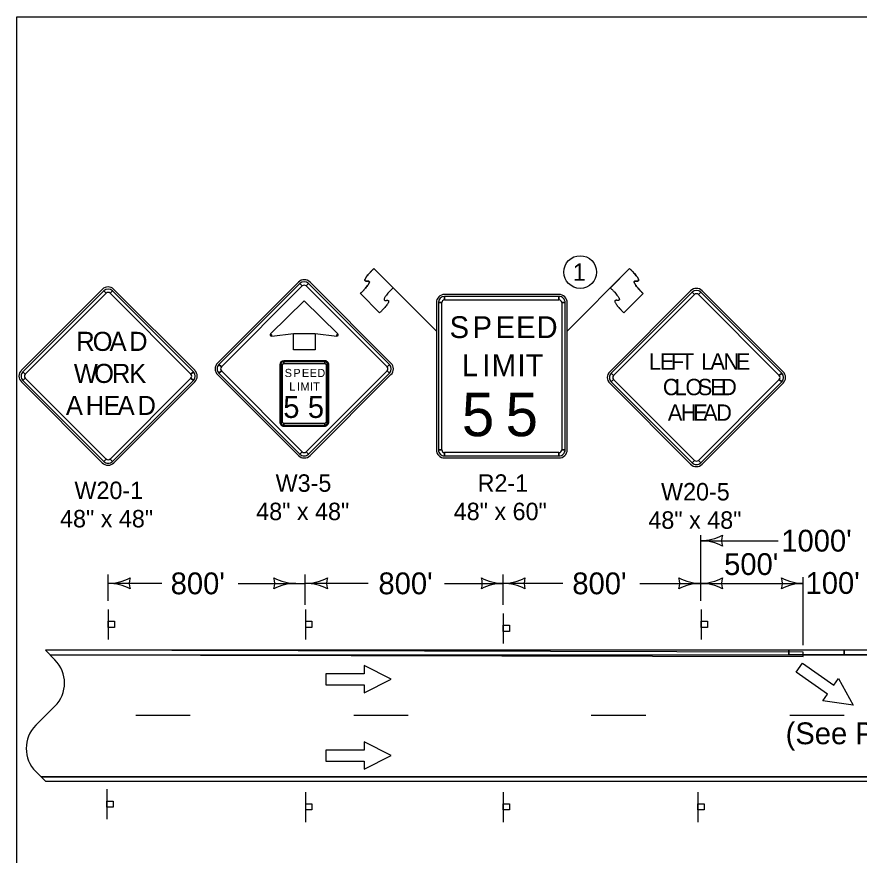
# Model space of a CAD drawing. Extents: x 10133 to 2270741, y 5363 to 1733450.
# Drawn here: x 24533 to 25305, y 9175 to 9944 of the extents above; entities that cross this region are included whole.
import ezdxf

# ---------------------------------------------------------------- set-up
doc = ezdxf.new("R2010")
doc.units = 0
for name, color, linetype in [('dsnNonPlotable', 7, 'Continuous'), ('dsnShtPlotShapeBatchPrint', 7, 'Continuous'), ('dsnStdBorder', 7, 'Continuous'), ('Level 12', 7, 'Continuous'), ('Level 2', 7, 'Continuous'), ('SheetBorder', 7, 'Continuous'), ('SheetText', 7, 'Continuous')]:
    doc.layers.add(name, color=color, linetype=linetype)

msp = doc.modelspace()

# ---------------------------------------------------------------- linework, layer by layer
at = {"layer": 'dsnNonPlotable'}
for p, q in [((24567.46, 9354.26), (24558.68, 9363.04)), ((24562.66, 9359.06), (25758.9, 9359.06)), ((25247.47, 9342.98), (25253.2, 9351.18)), ((25253.2, 9351.18), (25281.87, 9331.11)), ((25276.13, 9322.91), (25247.47, 9342.98)), ((25281.87, 9331.11), (25286.17, 9337.25)), ((25286.17, 9337.25), (25299.48, 9312.67)), ((25271.83, 9316.77), (25276.13, 9322.91)), ((24549.89, 9294.27), (24567.46, 9311.84)), ((25299.48, 9312.67), (25271.83, 9316.77)), ((24558.68, 9243.06), (24549.89, 9251.85)), ((24554.7, 9247.04), (26172.85, 9247.04))]:
    msp.add_line(p, q, dxfattribs=at)
for points in [[(24641.51, 9303.46), (24691.5, 9303.46)], [(24841.48, 9303.46), (24891.47, 9303.46)], [(25059.45, 9303.46), (25109.44, 9303.46)], [(25241.41, 9303.46), (25291.41, 9303.46)]]:
    msp.add_lwpolyline(points, dxfattribs=at)
for centre, start, end in [((24546.25, 9333.05), 315, 45), ((24571.1, 9273.06), 135, 225)]:
    msp.add_arc(centre, 30, start, end, dxfattribs=at)
at = {"layer": 'dsnShtPlotShapeBatchPrint'}
msp.add_circle((25049.25, 9709.97), 15, dxfattribs=at)
at = {"layer": 'dsnStdBorder'}
for p, q in [((24917.3, 9655.88), (24859.98, 9713.2)), ((24859.98, 9713.2), (24877.67, 9695.51)), ((25037.3, 9655.88), (25094.62, 9713.2)), ((25094.62, 9713.2), (25076.94, 9695.51)), ((24790.82, 9700.73), (24716.58, 9626.48)), ((24792.15, 9699.4), (24794.36, 9697.19)), ((24797.9, 9697.19), (24800.1, 9699.4)), ((24875.68, 9626.48), (24801.43, 9700.73)), ((24610.92, 9694.07), (24536.67, 9619.83)), ((24612.24, 9692.75), (24614.45, 9690.54)), ((24617.99, 9690.54), (24620.2, 9692.75)), ((24695.77, 9619.83), (24621.52, 9694.07)), ((24847.61, 9690.21), (24865.28, 9672.53)), ((24865.28, 9672.53), (24847.61, 9690.21)), ((25029.8, 9689.43), (24924.8, 9689.43)), ((25150.55, 9692.82), (25076.3, 9618.57)), ((25107, 9690.21), (25089.32, 9672.53)), ((25089.32, 9672.53), (25107, 9690.21)), ((25151.87, 9691.49), (25154.08, 9689.28)), ((25157.62, 9689.28), (25159.83, 9691.49)), ((25235.4, 9618.57), (25161.15, 9692.82)), ((24917.3, 9681.93), (24917.3, 9546.93)), ((24919.18, 9681.93), (24922.3, 9681.93)), ((24924.8, 9684.43), (24924.8, 9687.56)), ((25029.8, 9687.56), (25029.8, 9684.43)), ((25032.3, 9681.93), (25035.43, 9681.93)), ((25037.3, 9546.93), (25037.3, 9681.93)), ((24766.13, 9652.43), (24765.24, 9653.31)), ((24766.28, 9651.19), (24766.13, 9652.43)), ((24826.13, 9652.43), (24825.97, 9651.19)), ((24827.01, 9653.31), (24826.13, 9652.43)), ((24814.88, 9628.68), (24777.38, 9628.68)), ((24777.38, 9626.18), (24777.38, 9627.74)), ((24814.88, 9627.74), (24814.88, 9626.18)), ((24720.11, 9622.94), (24717.9, 9625.15)), ((24717.9, 9617.2), (24720.11, 9619.41)), ((24773.63, 9624.93), (24773.63, 9572.43)), ((24774.56, 9624.93), (24776.13, 9624.93)), ((24816.13, 9624.93), (24817.69, 9624.93)), ((24818.63, 9572.43), (24818.63, 9624.93)), ((24874.35, 9625.15), (24872.14, 9622.94)), ((24872.14, 9619.41), (24874.35, 9617.2)), ((24540.21, 9616.29), (24538, 9618.5)), ((24538, 9610.55), (24540.21, 9612.76)), ((24694.44, 9618.5), (24692.24, 9616.29)), ((24692.24, 9612.76), (24694.44, 9610.55)), ((24716.58, 9615.87), (24790.82, 9541.63)), ((24801.43, 9541.63), (24875.68, 9615.87)), ((25079.83, 9615.04), (25077.63, 9617.25)), ((25077.63, 9609.29), (25079.83, 9611.5)), ((25234.07, 9617.25), (25231.86, 9615.04)), ((25231.86, 9611.5), (25234.07, 9609.29)), ((24536.67, 9609.22), (24610.92, 9534.97)), ((24621.52, 9534.97), (24695.77, 9609.22)), ((25076.3, 9607.97), (25150.55, 9533.72)), ((25161.15, 9533.72), (25235.4, 9607.97)), ((24776.13, 9572.43), (24774.56, 9572.43)), ((24817.69, 9572.43), (24816.13, 9572.43)), ((24777.38, 9569.61), (24777.38, 9571.18)), ((24777.38, 9568.68), (24814.88, 9568.68)), ((24814.88, 9571.18), (24814.88, 9569.61)), ((24794.36, 9545.16), (24792.15, 9542.95)), ((24800.1, 9542.95), (24797.9, 9545.16)), ((24922.3, 9546.93), (24919.18, 9546.93)), ((24924.8, 9541.31), (24924.8, 9544.43)), ((25029.8, 9544.43), (25029.8, 9541.31)), ((25035.43, 9546.93), (25032.3, 9546.93)), ((24614.45, 9538.51), (24612.24, 9536.3)), ((24620.2, 9536.3), (24617.99, 9538.51)), ((24924.8, 9539.43), (25029.8, 9539.43)), ((25154.08, 9537.26), (25151.87, 9535.05)), ((25159.83, 9535.05), (25157.62, 9537.26)), ((24616.22, 9400.56), (24616.22, 9373.06)), ((24797.42, 9400.56), (24797.42, 9373.06)), ((24978.61, 9396.83), (24978.61, 9369.33)), ((25160.24, 9400.56), (25160.24, 9373.06)), ((24615.02, 9235.59), (24615.02, 9208.09)), ((24797.42, 9233.06), (24797.42, 9205.56)), ((24978.59, 9233.06), (24978.59, 9205.56)), ((25157.14, 9233.06), (25157.14, 9205.56))]:
    msp.add_line(p, q, dxfattribs=at)
for points in [[(24792.15, 9699.4), (24717.9, 9625.15), (24720.11, 9622.94), (24794.36, 9697.19), (24792.15, 9699.4)], [(24874.35, 9625.15), (24800.1, 9699.4), (24797.9, 9697.19), (24872.14, 9622.94), (24874.35, 9625.15)], [(24612.24, 9692.75), (24538, 9618.5), (24540.21, 9616.29), (24614.45, 9690.54), (24612.24, 9692.75)], [(24694.44, 9618.5), (24620.2, 9692.75), (24617.99, 9690.54), (24692.24, 9616.29), (24694.44, 9618.5)], [(25151.87, 9691.49), (25077.63, 9617.25), (25079.83, 9615.04), (25154.08, 9689.28), (25151.87, 9691.49)], [(25234.07, 9617.25), (25159.83, 9691.49), (25157.62, 9689.28), (25231.86, 9615.04), (25234.07, 9617.25)], [(24796.13, 9683.68), (24765.24, 9653.31), (24766.13, 9652.43), (24766.28, 9651.19), (24786.13, 9653.68), (24806.13, 9653.68), (24825.97, 9651.19), (24826.13, 9652.43), (24827.01, 9653.31), (24796.13, 9683.68)], [(24919.18, 9681.93), (24919.18, 9546.93), (24922.3, 9546.93), (24922.3, 9681.93), (24919.18, 9681.93)], [(25029.8, 9687.56), (24924.8, 9687.56), (24924.8, 9684.43), (25029.8, 9684.43), (25029.8, 9687.56)], [(25035.43, 9546.93), (25035.43, 9681.93), (25032.3, 9681.93), (25032.3, 9546.93), (25035.43, 9546.93)], [(24806.13, 9638.68), (24786.13, 9638.68), (24786.13, 9653.68), (24806.13, 9653.68), (24806.13, 9638.68)], [(24814.88, 9627.74), (24777.38, 9627.74), (24777.38, 9626.18), (24814.88, 9626.18), (24814.88, 9627.74)], [(24717.9, 9617.2), (24792.15, 9542.95), (24794.36, 9545.16), (24720.11, 9619.41), (24717.9, 9617.2)], [(24774.56, 9624.93), (24774.56, 9572.43), (24776.13, 9572.43), (24776.13, 9624.93), (24774.56, 9624.93)], [(24800.1, 9542.95), (24874.35, 9617.2), (24872.14, 9619.41), (24797.9, 9545.16), (24800.1, 9542.95)], [(24817.69, 9572.43), (24817.69, 9624.93), (24816.13, 9624.93), (24816.13, 9572.43), (24817.69, 9572.43)], [(24538, 9610.55), (24612.24, 9536.3), (24614.45, 9538.51), (24540.21, 9612.76), (24538, 9610.55)], [(24620.2, 9536.3), (24694.44, 9610.55), (24692.24, 9612.76), (24617.99, 9538.51), (24620.2, 9536.3)], [(25077.63, 9609.29), (25151.87, 9535.05), (25154.08, 9537.26), (25079.83, 9611.5), (25077.63, 9609.29)], [(25159.83, 9535.05), (25234.07, 9609.29), (25231.86, 9611.5), (25157.62, 9537.26), (25159.83, 9535.05)], [(24777.38, 9569.61), (24814.88, 9569.61), (24814.88, 9571.18), (24777.38, 9571.18), (24777.38, 9569.61)], [(24924.8, 9541.31), (25029.8, 9541.31), (25029.8, 9544.43), (24924.8, 9544.43), (24924.8, 9541.31)], [(24616.32, 9384.11), (24616.32, 9389.74), (24621.94, 9389.74), (24621.94, 9384.11)], [(24797.51, 9384.11), (24797.51, 9389.74), (24803.14, 9389.74), (24803.14, 9384.11)], [(25160.33, 9384.11), (25160.33, 9389.74), (25165.96, 9389.74), (25165.96, 9384.11)], [(24978.71, 9380.38), (24978.71, 9386), (24984.33, 9386), (24984.33, 9380.38)], [(24615.11, 9219.14), (24615.11, 9224.77), (24620.74, 9224.77), (24620.74, 9219.14)], [(24797.51, 9216.61), (24797.51, 9222.24), (24803.14, 9222.24), (24803.14, 9216.61)], [(24978.69, 9216.61), (24978.69, 9222.24), (24984.31, 9222.24), (24984.31, 9216.61)], [(25157.23, 9216.61), (25157.23, 9222.24), (25162.86, 9222.24), (25162.86, 9216.61)]]:
    msp.add_lwpolyline(points, close=True, dxfattribs=at)
for centre, radius, start, end in [((24616.22, 9688.77), 7.5, 44.99999, 134.99974), ((24796.13, 9695.42), 7.5, 44.99999, 134.99974), ((24796.13, 9695.42), 5.62, 44.99999, 134.99974), ((24796.13, 9695.42), 2.5, 44.99999, 134.99974), ((24616.22, 9688.77), 5.62, 44.99999, 134.99974), ((24616.22, 9688.77), 2.5, 44.99999, 134.99974), ((24924.8, 9681.93), 7.5, 90.00021, 179.99985), ((25029.8, 9681.93), 7.5, 0, 90.00021), ((25155.85, 9687.52), 7.5, 44.99999, 134.99974), ((25155.85, 9687.52), 5.62, 44.99999, 134.99974), ((25155.85, 9687.52), 2.5, 44.99999, 134.99974), ((24924.8, 9681.93), 5.62, 90.00021, 179.99985), ((24924.8, 9681.93), 2.5, 90.00021, 179.99985), ((25029.8, 9681.93), 5.62, 0, 90.00021), ((25029.8, 9681.93), 2.5, 0, 90.00021), ((24766.13, 9652.43), 1.25, 134.99974, 277.15286), ((24826.13, 9652.43), 1.25, 262.84725, 44.9998), ((24777.38, 9624.93), 3.75, 90.00021, 179.99985), ((24777.38, 9624.93), 2.81, 90.00021, 179.99985), ((24814.88, 9624.93), 3.75, 0, 90.00021), ((24814.88, 9624.93), 2.81, 0, 90.00021), ((24541.98, 9614.52), 7.5, 134.99974, 224.99995), ((24690.47, 9614.52), 7.5, 315.00016, 44.9998), ((24721.88, 9621.18), 7.5, 134.99974, 224.99995), ((24721.88, 9621.18), 5.62, 134.99974, 224.99995), ((24721.88, 9621.18), 2.5, 134.99974, 224.99995), ((24777.38, 9624.93), 1.25, 90.00021, 179.99985), ((24814.88, 9624.93), 1.25, 0, 90.00021), ((24870.37, 9621.18), 2.5, 315.00016, 44.9998), ((24870.37, 9621.18), 5.62, 315.00016, 44.9998), ((24870.37, 9621.18), 7.5, 315.00016, 44.9998), ((24541.98, 9614.52), 5.62, 134.99974, 224.99995), ((24541.98, 9614.52), 2.5, 134.99974, 224.99995), ((24690.47, 9614.52), 2.5, 315.00016, 44.9998), ((24690.47, 9614.52), 5.62, 315.00016, 44.9998), ((25081.6, 9613.27), 7.5, 134.99974, 224.99995), ((25081.6, 9613.27), 5.62, 134.99974, 224.99995), ((25081.6, 9613.27), 2.5, 134.99974, 224.99995), ((25230.09, 9613.27), 2.5, 315.00016, 44.9998), ((25230.09, 9613.27), 5.62, 315.00016, 44.9998), ((25230.09, 9613.27), 7.5, 315.00016, 44.9998), ((24777.38, 9572.43), 3.75, 179.99985, 270.00006), ((24777.38, 9572.43), 2.81, 179.99985, 270.00006), ((24777.38, 9572.43), 1.25, 179.99985, 270.00006), ((24814.88, 9572.43), 3.75, 270.00006, 0.00027), ((24814.88, 9572.43), 2.81, 270.00006, 0.00027), ((24814.88, 9572.43), 1.25, 270.00006, 0.00027), ((24796.13, 9546.93), 7.5, 224.99995, 315.00016), ((24796.13, 9546.93), 5.62, 224.99995, 315.00016), ((24796.13, 9546.93), 2.5, 224.99995, 315.00016), ((24924.8, 9546.93), 7.5, 179.99985, 270.00006), ((24924.8, 9546.93), 5.62, 179.99985, 270.00006), ((24924.8, 9546.93), 2.5, 179.99985, 270.00006), ((25029.8, 9546.93), 7.5, 270.00006, 0.00027), ((25029.8, 9546.93), 5.62, 270.00006, 0.00027), ((25029.8, 9546.93), 2.5, 270.00006, 0.00027), ((24616.22, 9540.28), 7.5, 224.99995, 315.00016), ((24616.22, 9540.28), 5.62, 224.99995, 315.00016), ((24616.22, 9540.28), 2.5, 224.99995, 315.00016), ((25155.85, 9539.02), 5.62, 224.99995, 315.00016), ((25155.85, 9539.02), 2.5, 224.99995, 315.00016), ((25155.85, 9539.02), 7.5, 224.99995, 315.00016)]:
    msp.add_arc(centre, radius, start, end, dxfattribs=at)
for points in [[(24859.98, 9713.2), (24847.61, 9700.81), (24859.98, 9702.58), (24847.61, 9690.21)], [(24847.61, 9690.21), (24859.98, 9702.58), (24847.61, 9700.81), (24859.98, 9713.2)], [(25094.62, 9713.2), (25107, 9700.81), (25094.62, 9702.58), (25107, 9690.21)], [(25107, 9690.21), (25094.62, 9702.58), (25107, 9700.81), (25094.62, 9713.2)], [(24877.67, 9695.51), (24865.29, 9683.13), (24877.66, 9684.9), (24865.28, 9672.53)], [(24877.67, 9695.51), (24865.29, 9683.13), (24877.66, 9684.9), (24865.28, 9672.53)], [(25076.94, 9695.51), (25089.32, 9683.13), (25076.95, 9684.9), (25089.32, 9672.53)], [(25076.94, 9695.51), (25089.32, 9683.13), (25076.95, 9684.9), (25089.32, 9672.53)]]:
    msp.add_open_spline(points, degree=2, dxfattribs=at)
at = {"layer": 'Level 12'}
for p, q in [((25159.79, 9408.56), (25159.79, 9468.6)), ((25159.59, 9463.6), (25230.82, 9463.6)), ((24616.22, 9408.56), (24616.22, 9432.57)), ((24797.03, 9404.83), (24797.03, 9432.57)), ((24978.61, 9404.83), (24978.61, 9432.57)), ((25253.89, 9367.79), (25253.89, 9430.03)), ((24665.58, 9424.45), (24619.02, 9424.45)), ((24735.61, 9424.45), (24797.03, 9424.45)), ((24854.89, 9424.45), (24797.03, 9424.45)), ((24924.91, 9424.45), (24978.61, 9424.45)), ((25033.2, 9424.45), (24978.61, 9424.45)), ((25103.97, 9424.45), (25159.59, 9424.45)), ((25160.39, 9424.45), (25228.11, 9424.45)), ((25228.11, 9424.45), (25253.89, 9424.45))]:
    msp.add_line(p, q, dxfattribs=at)
for centre, radius, start, end in [((25159.79, 9506.1), 42.5, 270, 298.07249), ((25195.42, 9463.6), 16.42, 162.26665, 197.73335), ((25159.79, 9421.1), 42.5, 61.92751, 90), ((24616.33, 9466.95), 42.5, 270, 298.07249), ((24651.97, 9424.45), 16.42, 162.26665, 197.73335), ((24752.68, 9424.45), 16.42, 342.26665, 17.73335), ((24788.32, 9466.95), 42.5, 241.92751, 270), ((24797.42, 9466.95), 42.5, 270, 298.07249), ((24833.05, 9424.45), 16.42, 162.26665, 197.73335), ((24942.96, 9424.45), 16.42, 342.26665, 17.73335), ((24978.59, 9466.95), 42.5, 241.92751, 270), ((24978.59, 9466.95), 42.5, 270, 298.07249), ((25014.23, 9424.45), 16.42, 162.26665, 197.73335), ((25124.15, 9424.45), 16.42, 342.26665, 17.73335), ((25159.79, 9466.95), 42.5, 241.92751, 270), ((25159.79, 9466.95), 42.5, 270, 298.07249), ((25195.42, 9424.45), 16.42, 162.26665, 197.73335), ((25218.25, 9424.45), 16.42, 342.26665, 17.73335), ((25253.89, 9466.95), 42.5, 241.92751, 270), ((24616.33, 9381.95), 42.5, 61.92751, 90), ((24788.32, 9381.95), 42.5, 90, 118.07249), ((24797.42, 9381.95), 42.5, 61.92751, 90), ((24978.59, 9381.95), 42.5, 90, 118.07249), ((24978.59, 9381.95), 42.5, 61.92751, 90), ((25159.79, 9381.95), 42.5, 90, 118.07249), ((25159.79, 9381.95), 42.5, 61.92751, 90), ((25253.89, 9381.95), 42.5, 90, 118.07249)]:
    msp.add_arc(centre, radius, start, end, dxfattribs=at)
at = {"layer": 'Level 2'}
for p, q in [((25240.68, 9363.06), (24558.68, 9363.06)), ((24558.68, 9363.06), (24567.46, 9354.26)), ((25253.89, 9361.36), (24558.68, 9363.06)), ((24562.67, 9359.06), (25253.89, 9357.36)), ((25240.68, 9359.06), (25240.68, 9363.06)), ((25291.5, 9363.06), (25240.68, 9363.06)), ((25240.68, 9363.06), (25240.68, 9359.06)), ((25240.68, 9359.06), (25291.5, 9359.06)), ((25253.89, 9357.36), (25253.89, 9361.36)), ((25483.46, 9363.06), (25291.5, 9363.06)), ((25291.5, 9363.06), (25291.5, 9359.06)), ((25291.5, 9359.06), (25291.5, 9363.06)), ((25291.5, 9359.06), (25483.46, 9359.06)), ((24567.46, 9311.84), (24549.89, 9294.27)), ((24549.89, 9251.85), (24554.68, 9247.06)), ((25938.21, 9247.06), (24554.68, 9247.06)), ((24554.68, 9247.06), (24558.68, 9243.06)), ((24554.68, 9247.06), (25389.45, 9247.06)), ((24558.68, 9243.06), (25964.98, 9243.06)), ((24558.68, 9243.06), (25936.49, 9243.06))]:
    msp.add_line(p, q, dxfattribs=at)
for points in [[(24558.68, 9363.06), (24562.66, 9359.07), (24562.67, 9359.06)], [(25389.45, 9359.06), (25291.5, 9359.06), (25240.68, 9359.06)], [(24554.68, 9247.06), (24554.68, 9247.06)], [(24554.68, 9247.06), (24554.68, 9247.06)]]:
    msp.add_lwpolyline(points, dxfattribs=at)
for centre, start, end in [((24546.25, 9333.05), 315, 45), ((24571.1, 9273.06), 135, 225)]:
    msp.add_arc(centre, 30, start, end, dxfattribs=at)
at = {"layer": 'SheetBorder'}
msp.add_lwpolyline([(24532.52, 9944.02), (27667.53, 9944.02), (27667.53, 7924.02), (24532.52, 7924.02)], close=True, dxfattribs=at)
at = {"layer": 'SheetText'}
for points in [[(24815.99, 9341.51), (24815.99, 9331.51), (24850.99, 9331.51), (24850.99, 9324.01), (24875.99, 9336.51), (24850.99, 9349.01), (24850.99, 9341.51), (24815.99, 9341.51)], [(24815.99, 9271.53), (24815.99, 9261.53), (24850.99, 9261.53), (24850.99, 9254.03), (24875.99, 9266.53), (24850.99, 9279.03), (24850.99, 9271.53), (24815.99, 9271.53)]]:
    msp.add_lwpolyline(points, dxfattribs=at)

# ---------------------------------------------------------------- texts
at = {"layer": 'dsnShtPlotShapeBatchPrint'}
msp.add_text('1', height=16, dxfattribs=at).set_placement((25042.55, 9701.97))
at = {"layer": 'dsnStdBorder'}
for s, height, p in [('S', 20, (24929.43, 9649.43)), ('P', 20, (24950.53, 9649.43)), ('E', 20, (24971.62, 9649.43)), ('E', 20, (24990.43, 9649.43)), ('D', 20, (25009.24, 9649.43)), ('R', 17.5, (24587.06, 9637.65)), ('O', 17.5, (24602.07, 9637.65)), ('A', 17.5, (24617.62, 9637.65)), ('D', 17.5, (24635.5, 9637.65)), ('L', 20, (24940.68, 9614.43)), ('I', 20, (24959.49, 9614.43)), ('M', 20, (24968.09, 9614.43)), ('I', 20, (24991.68, 9614.43)), ('T', 20, (24999.24, 9614.43)), ('L', 15, (25112.24, 9620.46)), ('E', 15, (25122.28, 9620.46)), ('F', 15, (25132.31, 9620.46)), ('T', 15, (25141.51, 9620.46)), ('L', 15, (25160.33, 9620.46)), ('A', 15, (25168.68, 9620.46)), ('N', 15, (25180.59, 9620.46)), ('E', 15, (25191.95, 9620.46)), ('W', 17.5, (24584.77, 9608.27)), ('O', 17.5, (24603.37, 9608.27)), ('R', 17.5, (24619.78, 9608.27)), ('K', 17.5, (24635.64, 9608.27)), ('S', 7.5, (24778.18, 9613.68)), ('P', 7.5, (24786.09, 9613.68)), ('E', 7.5, (24794, 9613.68)), ('E', 7.5, (24801.05, 9613.68)), ('D', 7.5, (24808.1, 9613.68)), ('C', 15, (25125.06, 9597.02)), ('L', 15, (25135.8, 9597.02)), ('O', 15, (25145.83, 9597.02)), ('S', 15, (25157.04, 9597.02)), ('E', 15, (25168.4, 9597.02)), ('D', 15, (25178.43, 9597.02)), ('L', 7.5, (24782.39, 9601.18)), ('I', 7.5, (24789.45, 9601.18)), ('M', 7.5, (24792.67, 9601.18)), ('I', 7.5, (24801.52, 9601.18)), ('T', 7.5, (24804.35, 9601.18)), ('A', 17.5, (24577.5, 9578.9)), ('H', 17.5, (24595.7, 9578.9)), ('E', 17.5, (24611.93, 9578.9)), ('A', 17.5, (24624.98, 9578.9)), ('D', 17.5, (24643.19, 9578.9)), ('5', 20, (24776.88, 9576.18)), ('5', 20, (24799.44, 9576.18)), ('5', 40, (24940.68, 9559.43)), ('5', 40, (24980.8, 9559.43)), ('A', 15, (25129.61, 9573.58)), ('H', 15, (25141.49, 9573.58)), ('E', 15, (25152.82, 9573.58)), ('A', 15, (25162, 9573.58)), ('D', 15, (25173.89, 9573.58)), ('W3-5', 16, (24769.88, 9508.43)), ('R2-1', 16, (24955.14, 9508.43)), ('W20-1', 16, (24585.37, 9501.78)), ('W20-5', 16, (25123.39, 9500.52)), ('48" x 48"', 16, (24752.06, 9482.43)), ('48" x 60"', 16, (24933.24, 9482.43)), ('48" x 48"', 16, (24572.15, 9475.78)), ('48" x 48"', 16, (25111.78, 9474.52)), ('(See PM-111)', 20, (25237.67, 9276.92))]:
    msp.add_text(s, height=height, dxfattribs=at).set_placement(p)
at = {"layer": 'Level 12'}
for s, p in [("1000'", (25233.7, 9453.6)), ("500'", (25181.26, 9432.12)), ("800'", (24673.61, 9414.45)), ("800'", (24864.2, 9414.45)), ("800'", (25042.02, 9414.45)), ("100'", (25255.96, 9414.82))]:
    msp.add_text(s, height=20, dxfattribs=at).set_placement(p)

doc.saveas('drawing.dxf')
